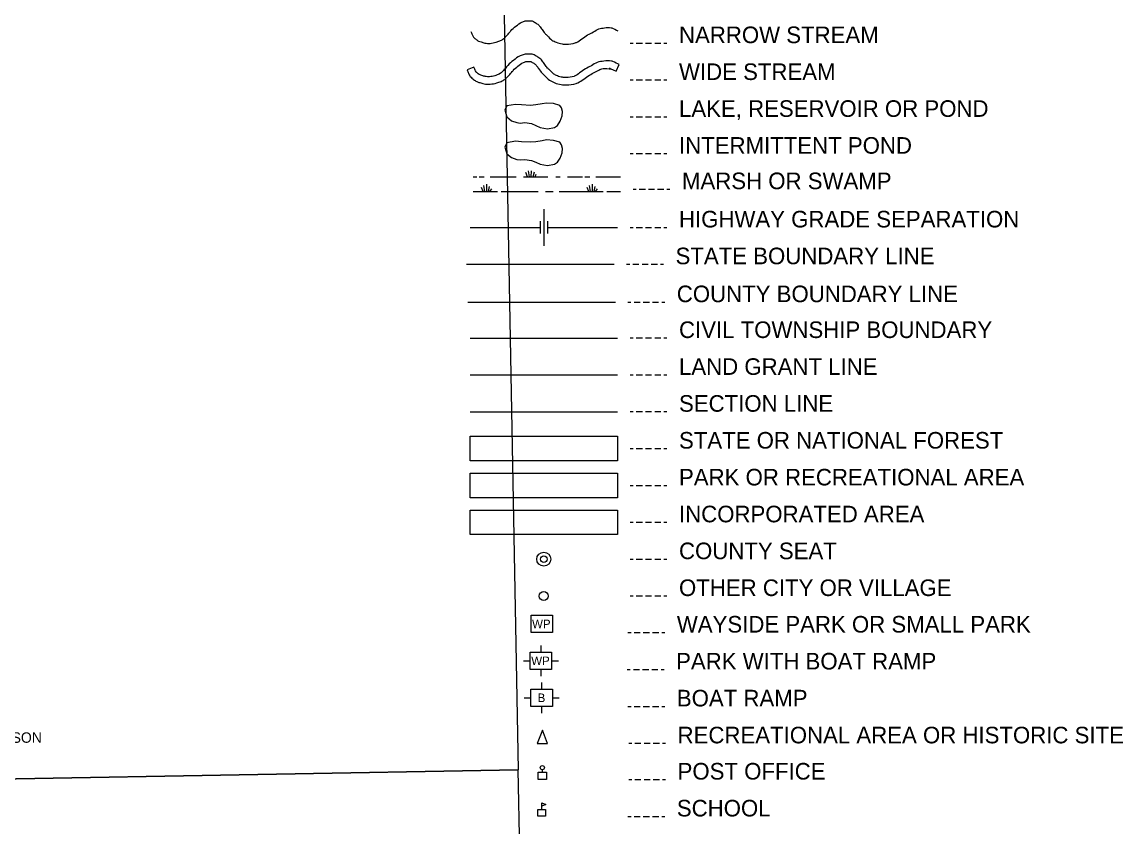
# Model space of a CAD drawing. Extents: x 2480962 to 2688785, y 277103 to 599240.
# Drawn here: x 2619276 to 2664059, y 458601 to 491360 of the extents above; entities that cross this region are included whole.
import ezdxf

# ---------------------------------------------------------------- set-up
doc = ezdxf.new("R2010")
doc.units = 0
for name, color, linetype in [('Divided_Highway', 7, 'Continuous'), ('Legend', 7, 'Continuous'), ('Roadshields County Roads', 7, 'Continuous')]:
    doc.layers.add(name, color=color, linetype=linetype)

msp = doc.modelspace()

# ---------------------------------------------------------------- linework, layer by layer
at = {"layer": 'Divided_Highway'}
for p, q in [((2638616.007, 506380.428), (2639463.689, 460928.527)), ((2638616.007, 506380.428), (2639463.689, 460928.527)), ((2600001.432, 460214.017), (2639463.689, 460928.527)), ((2639463.689, 460928.527), (2600001.432, 460214.017)), ((2600001.432, 460214.017), (2639463.689, 460928.527)), ((2639463.689, 460928.527), (2600001.432, 460214.017)), ((2639463.689, 460928.527), (2600001.432, 460214.017)), ((2640311.692, 415477.584), (2639463.689, 460928.527))]:
    msp.add_line(p, q, dxfattribs=at)
at = {"layer": 'Legend'}
for p, q in [((2637655.624, 489528.61), (2637378.682, 489413.274)), ((2643441.933, 489355.335), (2643569.921, 489626.663)), ((2637620.931, 485057.319), (2637770.931, 485057.319)), ((2637870.931, 485057.319), (2638078.18, 485057.319)), ((2638320.931, 485057.319), (2639370.931, 485057.319)), ((2639670.931, 485057.319), (2640658.304, 485057.319)), ((2639836.366, 485057.49), (2639770.895, 485229.356)), ((2639921.44, 485057.401), (2639876, 485307.319)), ((2639992.44, 485057.351), (2640006.074, 485307.319)), ((2640069.126, 485057.529), (2640127.361, 485261.348)), ((2640145.722, 485057.451), (2640194.607, 485166.083)), ((2640987.492, 485057.319), (2641170.931, 485057.319)), ((2641470.931, 485057.319), (2642070.931, 485057.319)), ((2642170.931, 485057.319), (2642378.18, 485057.319)), ((2642620.931, 485057.319), (2643620.931, 485057.319)), ((2638036.611, 484457.573), (2637970.542, 484630.368)), ((2638098.933, 484456.65), (2638059.542, 484709.885)), ((2638177.095, 484456.605), (2638182.826, 484760.319)), ((2638244.194, 484456.396), (2638287.081, 484662.247)), ((2638306.39, 484456.088), (2638390.169, 484569.788)), ((2642336.611, 484457.573), (2642270.542, 484630.368)), ((2642398.933, 484456.65), (2642359.542, 484709.885)), ((2642477.095, 484456.605), (2642482.826, 484760.319)), ((2642544.194, 484456.396), (2642587.081, 484662.247)), ((2642606.39, 484456.088), (2642690.169, 484569.788)), ((2637620.931, 484456.586), (2637870.931, 484456.586)), ((2637870.931, 484456.586), (2638620.931, 484456.586)), ((2638770.931, 484456.586), (2640270.931, 484456.586)), ((2640575.154, 484456.586), (2640885.445, 484456.586)), ((2641126.783, 484456.586), (2642170.931, 484456.586)), ((2642170.931, 484456.586), (2642920.931, 484456.586)), ((2643070.931, 484456.586), (2643620.931, 484456.586)), ((2640500, 483750), (2640500, 482250)), ((2640350, 483250), (2640350, 482750)), ((2640650, 483250), (2640650, 482750)), ((2637500, 483000), (2640346.307, 483000)), ((2640652.492, 483000), (2643500, 483000)), ((2637359.447, 481502.755), (2643359.447, 481502.755)), ((2637410.683, 479958.83), (2643410.683, 479958.83)), ((2637500, 478500), (2643500, 478500)), ((2637500, 477000), (2643500, 477000)), ((2637500, 475500), (2643500, 475500)), ((2640382.416, 465986.958), (2640382.416, 465711.958)), ((2639670.901, 465361.288), (2639945.901, 465361.288)), ((2640818.93, 465361.288), (2641093.914, 465361.288)), ((2640382.416, 465010.617), (2640382.416, 464735.616)), ((2640412.451, 464484.185), (2640412.451, 464209.185)), ((2639700.936, 463858.515), (2639975.936, 463858.515)), ((2640848.965, 463858.515), (2641123.949, 463858.515)), ((2640412.451, 463507.844), (2640412.451, 463232.843)), ((2640441.256, 460830.182), (2640441.256, 460926.177)), ((2640413.832, 459315.411), (2640413.832, 459450.788))]:
    msp.add_line(p, q, dxfattribs=at)
for points in [[(2644010.711, 490503.08), (2644135.711, 490503.08)], [(2644260.711, 490503.08), (2644510.711, 490503.08)], [(2644635.711, 490503.08), (2644885.711, 490503.08)], [(2645010.711, 490503.08), (2645260.711, 490503.08)], [(2645385.711, 490503.08), (2645510.711, 490503.08)], [(2644010.711, 489003.08), (2644135.711, 489003.08)], [(2644260.711, 489003.08), (2644510.711, 489003.08)], [(2644635.711, 489003.08), (2644885.711, 489003.08)], [(2645010.711, 489003.08), (2645260.711, 489003.08)], [(2645385.711, 489003.08), (2645510.711, 489003.08)], [(2644010.711, 487503.08), (2644135.711, 487503.08)], [(2644260.711, 487503.08), (2644510.711, 487503.08)], [(2644635.711, 487503.08), (2644885.711, 487503.08)], [(2645010.711, 487503.08), (2645260.711, 487503.08)], [(2645385.711, 487503.08), (2645510.711, 487503.08)], [(2644010.711, 486003.08), (2644135.711, 486003.08)], [(2644260.711, 486003.08), (2644510.711, 486003.08)], [(2644635.711, 486003.08), (2644885.711, 486003.08)], [(2645010.711, 486003.08), (2645260.711, 486003.08)], [(2645385.711, 486003.08), (2645510.711, 486003.08)], [(2644131.642, 484560.399), (2644256.642, 484560.399)], [(2644381.642, 484560.399), (2644631.642, 484560.399)], [(2644756.642, 484560.399), (2645006.642, 484560.399)], [(2645131.642, 484560.399), (2645381.642, 484560.399)], [(2645506.642, 484560.399), (2645631.642, 484560.399)], [(2644010.711, 483003.08), (2644135.711, 483003.08)], [(2644260.711, 483003.08), (2644510.711, 483003.08)], [(2644635.711, 483003.08), (2644885.711, 483003.08)], [(2645010.711, 483003.08), (2645260.711, 483003.08)], [(2645385.711, 483003.08), (2645510.711, 483003.08)], [(2643870.158, 481505.835), (2643995.158, 481505.835)], [(2644120.158, 481505.835), (2644370.158, 481505.835)], [(2644495.158, 481505.835), (2644745.158, 481505.835)], [(2644870.158, 481505.835), (2645120.158, 481505.835)], [(2645245.158, 481505.835), (2645370.158, 481505.835)], [(2643921.394, 479961.91), (2644046.394, 479961.91)], [(2644171.394, 479961.91), (2644421.394, 479961.91)], [(2644546.394, 479961.91), (2644796.394, 479961.91)], [(2644921.394, 479961.91), (2645171.394, 479961.91)], [(2645296.394, 479961.91), (2645421.394, 479961.91)], [(2644010.711, 478503.08), (2644135.711, 478503.08)], [(2644260.711, 478503.08), (2644510.711, 478503.08)], [(2644635.711, 478503.08), (2644885.711, 478503.08)], [(2645010.711, 478503.08), (2645260.711, 478503.08)], [(2645385.711, 478503.08), (2645510.711, 478503.08)], [(2644010.711, 477003.08), (2644135.711, 477003.08)], [(2644260.711, 477003.08), (2644510.711, 477003.08)], [(2644635.711, 477003.08), (2644885.711, 477003.08)], [(2645010.711, 477003.08), (2645260.711, 477003.08)], [(2645385.711, 477003.08), (2645510.711, 477003.08)], [(2644010.711, 475503.08), (2644135.711, 475503.08)], [(2644260.711, 475503.08), (2644510.711, 475503.08)], [(2644635.711, 475503.08), (2644885.711, 475503.08)], [(2645010.711, 475503.08), (2645260.711, 475503.08)], [(2645385.711, 475503.08), (2645510.711, 475503.08)], [(2644010.711, 474003.08), (2644135.711, 474003.08)], [(2644260.711, 474003.08), (2644510.711, 474003.08)], [(2644635.711, 474003.08), (2644885.711, 474003.08)], [(2645010.711, 474003.08), (2645260.711, 474003.08)], [(2645385.711, 474003.08), (2645510.711, 474003.08)], [(2644010.711, 472503.08), (2644135.711, 472503.08)], [(2644260.711, 472503.08), (2644510.711, 472503.08)], [(2644635.711, 472503.08), (2644885.711, 472503.08)], [(2645010.711, 472503.08), (2645260.711, 472503.08)], [(2645385.711, 472503.08), (2645510.711, 472503.08)], [(2644010.711, 471003.08), (2644135.711, 471003.08)], [(2644260.711, 471003.08), (2644510.711, 471003.08)], [(2644635.711, 471003.08), (2644885.711, 471003.08)], [(2645010.711, 471003.08), (2645260.711, 471003.08)], [(2645385.711, 471003.08), (2645510.711, 471003.08)], [(2644010.711, 469503.08), (2644135.711, 469503.08)], [(2644260.711, 469503.08), (2644510.711, 469503.08)], [(2644635.711, 469503.08), (2644885.711, 469503.08)], [(2645010.711, 469503.08), (2645260.711, 469503.08)], [(2645385.711, 469503.08), (2645510.711, 469503.08)], [(2644010.711, 468003.08), (2644135.711, 468003.08)], [(2644260.711, 468003.08), (2644510.711, 468003.08)], [(2644635.711, 468003.08), (2644885.711, 468003.08)], [(2645010.711, 468003.08), (2645260.711, 468003.08)], [(2645385.711, 468003.08), (2645510.711, 468003.08)], [(2643923.162, 466516.471), (2644048.162, 466516.471)], [(2644173.162, 466516.471), (2644423.162, 466516.471)], [(2644548.162, 466516.471), (2644798.162, 466516.471)], [(2644923.162, 466516.471), (2645173.162, 466516.471)], [(2645298.162, 466516.471), (2645423.162, 466516.471)], [(2643893.127, 465013.697), (2644018.127, 465013.697)], [(2644143.127, 465013.697), (2644393.127, 465013.697)], [(2644518.127, 465013.697), (2644768.127, 465013.697)], [(2644893.127, 465013.697), (2645143.127, 465013.697)], [(2645268.127, 465013.697), (2645393.127, 465013.697)], [(2643923.162, 463510.924), (2644048.162, 463510.924)], [(2644173.162, 463510.924), (2644423.162, 463510.924)], [(2644548.162, 463510.924), (2644798.162, 463510.924)], [(2644923.162, 463510.924), (2645173.162, 463510.924)], [(2645298.162, 463510.924), (2645423.162, 463510.924)], [(2643953.197, 462008.15), (2644078.197, 462008.15)], [(2644203.197, 462008.15), (2644453.197, 462008.15)], [(2644578.197, 462008.15), (2644828.197, 462008.15)], [(2644953.197, 462008.15), (2645203.197, 462008.15)], [(2645328.197, 462008.15), (2645453.197, 462008.15)], [(2643953.197, 460535.431), (2644078.197, 460535.431)], [(2644203.197, 460535.431), (2644453.197, 460535.431)], [(2644578.197, 460535.431), (2644828.197, 460535.431)], [(2644953.197, 460535.431), (2645203.197, 460535.431)], [(2645328.197, 460535.431), (2645453.197, 460535.431)], [(2643923.162, 459032.657), (2644048.162, 459032.657)], [(2644173.162, 459032.657), (2644423.162, 459032.657)], [(2644548.162, 459032.657), (2644798.162, 459032.657)], [(2644923.162, 459032.657), (2645173.162, 459032.657)], [(2645298.162, 459032.657), (2645423.162, 459032.657)]]:
    msp.add_lwpolyline(points, dxfattribs=at)
for points in [[(2639000, 487500), (2639189.159, 487343.96), (2639402.615, 487266.303), (2639538.451, 487246.888), (2639732.503, 487266.303), (2640004.175, 487227.474), (2640178.821, 487149.816), (2640353.467, 487072.159), (2640644.545, 487013.915), (2640935.622, 487072.159), (2641052.053, 487149.816), (2641168.483, 487324.546), (2641246.104, 487538.104), (2641265.509, 487712.834), (2641226.699, 487868.149), (2641149.078, 487965.221), (2640896.811, 488042.879), (2640605.734, 488062.293), (2640431.088, 488023.465), (2640178.821, 487984.636), (2639965.364, 487965.221), (2639596.667, 487984.636), (2639344.4, 488004.05), (2638995.107, 487945.807), (2638917.487, 487771.077)], [(2639000, 486000), (2639189.159, 485843.96), (2639402.615, 485766.303), (2639538.451, 485746.888), (2639732.503, 485766.303), (2640004.175, 485727.474), (2640178.821, 485649.816), (2640353.467, 485572.159), (2640644.545, 485513.915), (2640935.622, 485572.159), (2641052.053, 485649.816), (2641168.483, 485824.546), (2641246.104, 486038.104), (2641265.509, 486212.834), (2641226.699, 486368.149), (2641149.078, 486465.221), (2640896.811, 486542.879), (2640605.734, 486562.293), (2640431.088, 486523.465), (2640178.821, 486484.636), (2639965.364, 486465.221), (2639596.667, 486484.636), (2639344.4, 486504.05), (2638995.107, 486445.807), (2638917.487, 486271.077)], [(2637500, 474500), (2643500, 474500), (2643500, 473500), (2637500, 473500)], [(2637500, 473000), (2643500, 473000), (2643500, 472000), (2637500, 472000)], [(2637500, 471500), (2643500, 471500), (2643500, 470500), (2637500, 470500)], [(2639979.617, 467214.732), (2640852.646, 467214.732), (2640852.646, 466513.391), (2639979.617, 466513.391)], [(2639945.901, 465711.958), (2640818.93, 465711.958), (2640818.93, 465010.617), (2639945.901, 465010.617)], [(2639975.936, 464209.185), (2640848.965, 464209.185), (2640848.965, 463507.844), (2639975.936, 463507.844)], [(2640440.639, 462544.119), (2640236.483, 462002.609), (2640644.796, 462002.609)], [(2640267.846, 460830.182), (2640614.667, 460830.182), (2640614.667, 460532.351), (2640267.846, 460532.351)], [(2640413.832, 459582.694), (2640586.324, 459511.669), (2640413.832, 459450.788)], [(2640251.49, 459315.411), (2640576.173, 459315.411), (2640576.173, 459034.81), (2640251.49, 459034.81)]]:
    msp.add_lwpolyline(points, close=True, dxfattribs=at)
for centre, radius in [((2640498.393, 469500), 284.821), ((2640500, 469500), 131.762), ((2640500, 468000), 183.973), ((2640441.256, 461014.787), 87.46)]:
    msp.add_circle(centre, radius, dxfattribs=at)
for points in [[(2637526.465, 490979.658), (2637581.911, 490846.523), (2637637.358, 490746.671), (2637748.252, 490646.819), (2637848.056, 490580.251), (2637947.86, 490546.967), (2638103.111, 490502.589), (2638313.808, 490491.494), (2638557.774, 490535.873), (2638713.025, 490591.346), (2638835.008, 490657.914), (2638979.169, 490791.049), (2639112.241, 490946.374), (2639156.599, 491001.847), (2639367.296, 491190.456), (2639611.262, 491356.876), (2639744.334, 491401.255), (2639810.87, 491412.349), (2639921.764, 491412.349), (2640032.657, 491401.255), (2640081.355, 491375.607), (2640221.176, 491290.308), (2640332.07, 491190.456), (2640427.039, 491051.833), (2640553.856, 490890.901), (2640644.012, 490801.644), (2640831.09, 490624.63), (2641008.52, 490535.873), (2641241.396, 490469.305), (2641418.826, 490458.21), (2641780.358, 490510.983), (2641824.488, 490529.38), (2642050.918, 490669.008), (2642283.795, 490835.428), (2642516.671, 490957.469), (2642738.458, 491079.51), (2642971.334, 491123.889), (2643234.348, 491129.028), (2643261.203, 491119.545), (2643515.239, 490999.715)], [(2643569.921, 489626.663), (2643309.007, 489749.738), (2643249.317, 489770.815), (2642946.406, 489764.897), (2642677.685, 489713.687), (2642436.381, 489580.906), (2642195.69, 489454.769), (2641958.538, 489285.295), (2641746.526, 489154.557), (2641730.727, 489147.971), (2641403.295, 489100.176), (2641257.675, 489109.282), (2641053.843, 489167.547), (2640908.744, 489240.131), (2640739.027, 489400.718), (2640656.642, 489482.282), (2640538.642, 489632.025), (2640436.406, 489781.256), (2640301.879, 489902.387), (2640146.126, 489997.406), (2640067.372, 490038.883), (2639919.936, 490053.633), (2639789.138, 490053.633), (2639698.737, 490038.56), (2639534.679, 489983.847), (2639265.297, 489800.09), (2639037.935, 489596.563), (2638987.364, 489533.32), (2638861.649, 489386.582), (2638737.557, 489271.981), (2638642.175, 489219.929), (2638509.545, 489172.539), (2638294.888, 489133.492), (2638118.672, 489142.771), (2637982.909, 489181.578), (2637905.26, 489207.474), (2637831.225, 489256.854), (2637747.027, 489332.669), (2637707.83, 489403.257), (2637655.624, 489528.61)], [(2637378.682, 489413.274), (2637437.368, 489272.357), (2637509.065, 489143.241), (2637646.655, 489019.352), (2637772.228, 488935.596), (2637894.187, 488894.924), (2638068.926, 488844.975), (2638314.104, 488832.064), (2638587.379, 488881.775), (2638765.251, 488945.331), (2638913.835, 489026.415), (2639078.065, 489178.084), (2639218.494, 489341.996), (2639256.639, 489389.699), (2639450.671, 489563.39), (2639669.221, 489712.473), (2639771.307, 489746.518), (2639813.978, 489753.633), (2639904.968, 489753.633), (2639979.318, 489746.195), (2639997.96, 489736.376), (2640121.849, 489660.797), (2640209.11, 489582.224), (2640296.812, 489454.209), (2640432.446, 489282.088), (2640530.373, 489185.138), (2640734.812, 488991.697), (2640944.573, 488886.767), (2641206.493, 488811.896), (2641415.733, 488798.812), (2641811.365, 488856.563), (2641883.826, 488886.771), (2642124.674, 489035.289), (2642353.276, 489198.655), (2642578.337, 489316.6), (2642780.607, 489427.901), (2642977.638, 489465.449), (2643200.755, 489469.809), (2643194.775, 489471.92), (2643441.933, 489355.335)]]:
    msp.add_spline(points, degree=3, dxfattribs=at)

# ---------------------------------------------------------------- texts
for s, height, p in [('NARROW STREAM', 675, (2646000, 490500)), ('WIDE STREAM', 675, (2646000, 489000)), ('LAKE, RESERVOIR OR POND', 675, (2646000, 487500)), ('INTERMITTENT POND', 675, (2646000, 486000)), ('MARSH OR SWAMP', 675, (2646120.931, 484557.319)), ('HIGHWAY GRADE SEPARATION', 675, (2646000, 483000)), ('STATE BOUNDARY LINE', 675, (2645859.447, 481502.755)), ('COUNTY BOUNDARY LINE', 675, (2645910.683, 479958.83)), ('CIVIL TOWNSHIP BOUNDARY', 675, (2646000, 478500)), ('LAND GRANT LINE', 675, (2646000, 477000)), ('SECTION LINE', 675, (2646000, 475500)), ('STATE OR NATIONAL FOREST', 675, (2646000, 474000)), ('PARK OR RECREATIONAL AREA', 675, (2646000, 472500)), ('INCORPORATED AREA', 675, (2646000, 471000)), ('COUNTY SEAT', 675, (2646000, 469500)), ('OTHER CITY OR VILLAGE', 675, (2646000, 468000)), ('WAYSIDE PARK OR SMALL PARK', 675, (2645912.451, 466513.391)), ('WP', 350, (2640022.512, 466690.673)), ('WP', 350, (2639988.796, 465187.899)), ('PARK WITH BOAT RAMP', 675, (2645882.416, 465010.617)), ('B', 350, (2640248.848, 463683.515)), ('BOAT RAMP', 675, (2645912.451, 463507.844)), ('RECREATIONAL AREA OR HISTORIC SITE', 675, (2645942.486, 462005.07)), ('POST OFFICE', 675, (2645942.486, 460532.351)), ('SCHOOL', 675, (2645912.451, 459029.577))]:
    msp.add_text(s, height=height, dxfattribs=at).set_placement(p)
at = {"layer": 'Roadshields County Roads'}
msp.add_text('SANDERSON', height=425, rotation=0.0287917, dxfattribs=at).set_placement((2616484.844, 462026.172))

doc.saveas('drawing.dxf')
